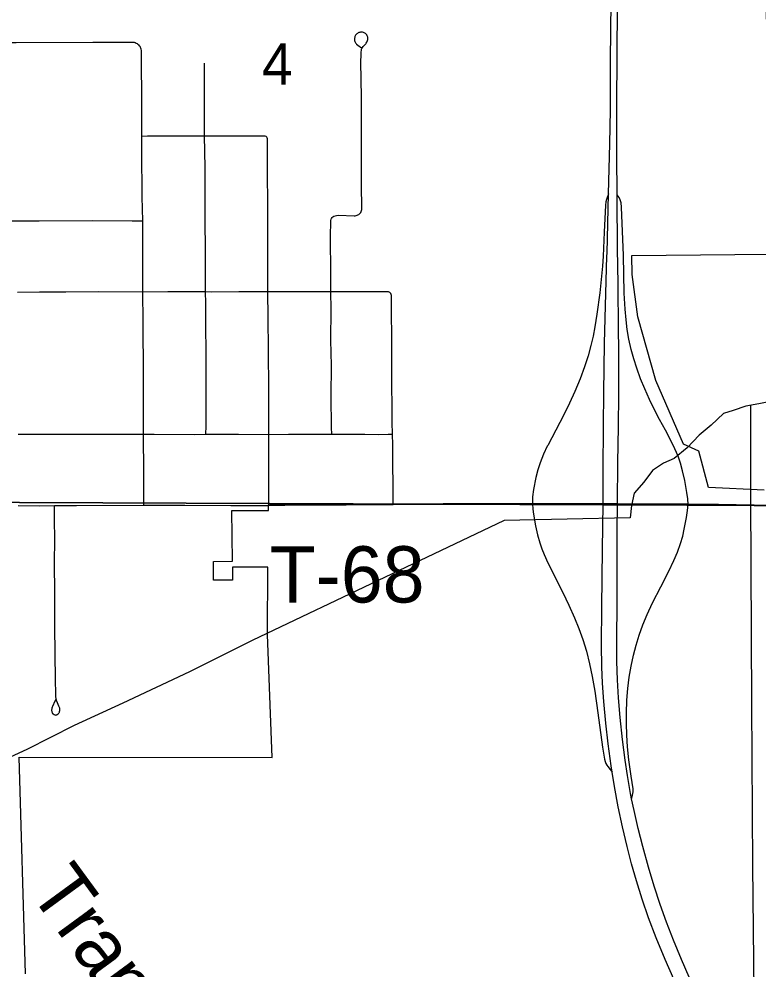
# Model space of a CAD drawing. Extents: x 0 to 40.2, y 0 to 22.
# Drawn here: x 4.998 to 5.744, y 14.848 to 15.808 of the extents above; entities that cross this region are included whole.
import ezdxf

# ---------------------------------------------------------------- set-up
doc = ezdxf.new("R2010")
doc.units = 0
for name, color, linetype in [('GM_X_City_Street', 7, 'Continuous'), ('GM_X_Corporation', 7, 'Continuous'), ('GM_X_County_Road_Text', 7, 'Continuous'), ('GM_X_Major_River_Text', 7, 'Continuous'), ('GM_X_Minor_Lake', 7, 'Continuous'), ('GM_X_Rail_Line', 7, 'Continuous'), ('GM_X_Unincorporated', 7, 'Continuous'), ('GM_X_Unincorporated_Location', 7, 'Continuous'), ('GM_X_US_Route', 7, 'Continuous')]:
    doc.layers.add(name, color=color, linetype=linetype)

msp = doc.modelspace()

# ---------------------------------------------------------------- linework, layer by layer
at = {"layer": 'GM_X_Corporation'}
for points in [[(5.74842, 16.25686), (5.75579, 15.31682), (4.745, 15.32081), (4.73985, 16.25627), (4.77053, 16.2552)], [(4.745, 15.32081), (5.75579, 15.31682), (5.76512, 14.30968), (4.74904, 14.31449)]]:
    msp.add_lwpolyline(points, close=True, dxfattribs=at)
for points in [[(5.74959, 15.33227), (5.69342, 15.33518), (5.68362, 15.37185), (5.6681, 15.37896), (5.64038, 15.44327), (5.62228, 15.50735), (5.61648, 15.55028), (5.61617, 15.56955), (5.75473, 15.57087)], [(5.0042, 14.84362), (4.99778, 15.0627), (5.25288, 15.0624), (5.24833, 15.18641), (5.24874, 15.25456), (5.21293, 15.25444), (5.21293, 15.24148), (5.1938, 15.24145), (5.19377, 15.26044), (5.2129, 15.26048), (5.21228, 15.31182), (5.24925, 15.31174), (5.24948, 15.31759), (5.26548, 15.31762), (5.32735, 15.31797), (5.37502, 15.31833), (5.42565, 15.31875), (5.42685, 15.31876), (5.51549, 15.31911), (5.57481, 15.31902), (5.58687, 15.31891), (5.60127, 15.31879), (5.63758, 15.31847), (5.67262, 15.3185), (5.70344, 15.31827), (5.73948, 15.31755), (5.75597, 15.31722)]]:
    msp.add_lwpolyline(points, dxfattribs=at)
at = {"layer": 'GM_X_Major_River_Text'}
for points in [[(5.59261, 15.63157), (5.5906, 15.62604), (5.59, 15.62363), (5.58939, 15.6201), (5.58824, 15.59307), (5.58725, 15.56876), (5.58659, 15.55857), (5.5837, 15.53167), (5.58091, 15.51009), (5.57888, 15.49719), (5.57709, 15.48803), (5.5748, 15.47835), (5.57195, 15.46817), (5.56832, 15.45692), (5.56384, 15.44466), (5.55866, 15.43199), (5.55327, 15.4201), (5.54745, 15.40841), (5.53119, 15.37761), (5.53076, 15.37671)], [(5.67285, 15.31794), (5.67246, 15.32345), (5.67164, 15.32988), (5.66948, 15.34212), (5.66733, 15.35183), (5.66514, 15.35961), (5.66271, 15.36666), (5.65958, 15.3741), (5.65552, 15.38249), (5.64993, 15.3929), (5.64402, 15.40383), (5.63973, 15.41211), (5.634, 15.42384), (5.62909, 15.43457), (5.62484, 15.44493), (5.62103, 15.45545), (5.61806, 15.46494), (5.6155, 15.47455), (5.61322, 15.48487), (5.6115, 15.49466), (5.61026, 15.50452), (5.60935, 15.51505), (5.60851, 15.5312), (5.60765, 15.56927), (5.60579, 15.61832), (5.6053, 15.62252), (5.60429, 15.62574), (5.60329, 15.62796), (5.6013, 15.63086)], [(5.53076, 15.37671), (5.52691, 15.36862), (5.52343, 15.35998), (5.52115, 15.35288), (5.51925, 15.34502), (5.51687, 15.33292), (5.51593, 15.32558), (5.51572, 15.31856)], [(5.51572, 15.31856), (5.51614, 15.31321), (5.51667, 15.30807), (5.51883, 15.29647), (5.52091, 15.28738), (5.52324, 15.279), (5.52522, 15.27312), (5.52746, 15.26733), (5.53139, 15.25888), (5.54655, 15.22894), (5.55265, 15.21603), (5.55815, 15.2035), (5.56258, 15.19256), (5.56665, 15.18148), (5.57032, 15.16961), (5.57349, 15.15695), (5.57613, 15.14418), (5.57864, 15.12947), (5.5818, 15.10732), (5.5865, 15.07284), (5.58845, 15.06057), (5.58911, 15.05828), (5.58999, 15.05621), (5.59095, 15.05445), (5.59182, 15.0531), (5.5941, 15.0501), (5.59622, 15.04732)], [(5.61591, 15.02067), (5.61685, 15.02419), (5.61719, 15.02587), (5.61742, 15.02755), (5.61746, 15.02902), (5.61736, 15.03071), (5.61535, 15.04336), (5.61312, 15.05999), (5.61175, 15.07296), (5.61093, 15.08474), (5.61055, 15.09653), (5.61059, 15.10709), (5.61114, 15.12012), (5.6121, 15.13189), (5.61354, 15.1436), (5.61537, 15.15463), (5.61768, 15.16557), (5.62033, 15.1758), (5.62343, 15.18589), (5.62723, 15.1964), (5.63155, 15.20671), (5.63709, 15.21852), (5.64525, 15.23458), (5.65343, 15.25064), (5.65845, 15.26131), (5.66211, 15.26988), (5.66532, 15.27863), (5.66743, 15.28577), (5.66906, 15.29304), (5.67117, 15.30478), (5.67216, 15.31182), (5.67285, 15.31794)]]:
    msp.add_lwpolyline(points, dxfattribs=at)
at = {"layer": 'GM_X_Minor_Lake'}
for points in [[(5.75447, 15.42161), (5.74423, 15.4195), (5.73132, 15.41706), (5.71839, 15.41271), (5.70851, 15.40984), (5.69622, 15.39789), (5.68395, 15.38785), (5.67202, 15.37514), (5.65899, 15.36435), (5.64794, 15.35959), (5.63685, 15.35218), (5.62834, 15.34056), (5.61833, 15.32934), (5.61586, 15.31686), (5.61453, 15.30436)], [(5.74043, 14.67702), (5.73999, 14.79276), (5.73835, 14.95291), (5.73716, 15.11646), (5.73631, 15.32554), (5.73624, 15.41799)], [(5.61453, 15.30436), (5.48737, 15.30186), (5.36653, 15.24424), (5.2335, 15.18075), (5.16943, 15.14878), (5.10235, 15.11723), (5.05318, 15.0945), (5.00551, 15.07023), (4.96207, 15.05044), (4.90609, 15.05096), (4.86182, 15.05092), (4.83658, 15.05739), (4.79141, 15.02435), (4.73825, 14.98803), (4.70954, 14.96649), (4.68877, 14.94519), (4.68027, 14.93357), (4.67593, 14.92263), (4.67861, 14.90058), (4.68093, 14.87968), (4.68138, 14.8607), (4.6766, 14.84484)]]:
    msp.add_lwpolyline(points, dxfattribs=at)
at = {"layer": 'GM_X_Rail_Line'}
msp.add_line((5.50277, 15.31851), (5.51572, 15.31856), dxfattribs=at)
for points in [[(4.99651, 15.31676), (5.01786, 15.31655), (5.03327, 15.31674)], [(5.03327, 15.31674), (5.05562, 15.31698), (5.12337, 15.31721)], [(5.12337, 15.31721), (5.16494, 15.3171), (5.21126, 15.31696)], [(5.21126, 15.31696), (5.21224, 15.31695), (5.2497, 15.31703)], [(5.2497, 15.31703), (5.26571, 15.31706), (5.32757, 15.31741), (5.37525, 15.31777)], [(5.37525, 15.31777), (5.42588, 15.31819), (5.42707, 15.3182), (5.50277, 15.31851)], [(5.51572, 15.31856), (5.57503, 15.31846), (5.5871, 15.31836), (5.60149, 15.31823), (5.6378, 15.31792), (5.67285, 15.31794)], [(5.67285, 15.31794), (5.70366, 15.31771), (5.73971, 15.317), (5.7562, 15.31667)]]:
    msp.add_lwpolyline(points, dxfattribs=at)
at = {"layer": 'GM_X_Unincorporated'}
for points in [[(5.59261, 15.63157), (5.59396, 15.68229), (5.59452, 15.71648), (5.59471, 15.76247), (5.59502, 15.80037), (5.5953, 15.82171), (5.59617, 15.93153), (5.59644, 15.97192), (5.59708, 16.01604), (5.59751, 16.05458), (5.59769, 16.08692), (5.59774, 16.14846), (5.59793, 16.17891), (5.59863, 16.25243), (5.59954, 16.34117), (5.59999, 16.39651)], [(5.60174, 15.573), (5.6013, 15.63086), (5.601, 15.67012), (5.60097, 15.72112), (5.6017, 15.82172)], [(5.58718, 15.32616), (5.58731, 15.35172), (5.58734, 15.39773), (5.58767, 15.43067), (5.58864, 15.48101), (5.59094, 15.56885), (5.59103, 15.57172), (5.59261, 15.63157)], [(5.6015, 15.31923), (5.60199, 15.36022), (5.60265, 15.39627), (5.60295, 15.42921), (5.60291, 15.46838), (5.6018, 15.56598), (5.60177, 15.56901), (5.60174, 15.573)], [(5.59622, 15.04732), (5.59515, 15.05392), (5.59208, 15.07606), (5.58971, 15.09705), (5.58779, 15.1187), (5.5866, 15.13729), (5.58595, 15.15404), (5.5856, 15.17578), (5.58568, 15.21432), (5.58634, 15.27275), (5.5871, 15.31836), (5.58715, 15.32125), (5.58718, 15.32616)], [(5.6738, 14.84051), (5.66613, 14.85822), (5.65809, 14.87779), (5.65114, 14.89579), (5.64462, 14.91395), (5.63858, 14.93228), (5.63286, 14.95136), (5.6271, 14.97237), (5.62256, 14.99049), (5.61836, 15.00868), (5.61591, 15.02067), (5.61487, 15.02576), (5.61159, 15.04415), (5.60924, 15.05953), (5.60654, 15.08053), (5.60433, 15.10283), (5.60279, 15.12268), (5.60175, 15.1407), (5.60111, 15.15937), (5.60092, 15.1799), (5.60117, 15.21909), (5.60136, 15.25452), (5.60118, 15.29181), (5.60149, 15.31823), (5.6015, 15.31923)], [(5.74645, 14.68727), (5.7284, 14.71332), (5.71567, 14.73246), (5.70512, 14.7493), (5.69373, 14.76854), (5.685, 14.78429), (5.67611, 14.80136), (5.66731, 14.81919), (5.6584, 14.83833), (5.64967, 14.85824), (5.64075, 14.88009), (5.63303, 14.90041), (5.62652, 14.91918), (5.62075, 14.93755), (5.6158, 14.95486), (5.61127, 14.97229), (5.60657, 14.99224), (5.60236, 15.0123), (5.59853, 15.03307), (5.59622, 15.04732)]]:
    msp.add_lwpolyline(points, dxfattribs=at)
at = {"layer": 'GM_X_Unincorporated_Location'}
for points in [[(5.31313, 15.38888), (5.31306, 15.39564), (5.31272, 15.42739), (5.31287, 15.45824), (5.31237, 15.48398), (5.31251, 15.51471), (5.31227, 15.53305), (5.31213, 15.54951), (5.31195, 15.58994), (5.31213, 15.60283), (5.31228, 15.60487), (5.31257, 15.60623), (5.313, 15.60696), (5.31351, 15.60771), (5.31425, 15.60845), (5.31524, 15.60907), (5.31648, 15.60964), (5.31787, 15.60993), (5.32012, 15.61001), (5.33584, 15.60959), (5.33669, 15.60964), (5.33785, 15.60983), (5.33877, 15.6101), (5.33967, 15.61046), (5.34048, 15.61089), (5.34132, 15.61142), (5.34193, 15.61207), (5.34255, 15.61298), (5.343, 15.61389), (5.34329, 15.61488), (5.34343, 15.61573), (5.34349, 15.61662), (5.3433, 15.64108), (5.34329, 15.65166), (5.34333, 15.6616), (5.34304, 15.68146), (5.34315, 15.70373), (5.3432, 15.72923), (5.3427, 15.76504), (5.34273, 15.77214), (5.34292, 15.77524), (5.3431, 15.77657), (5.34337, 15.77771), (5.34365, 15.77863), (5.34408, 15.7795), (5.34479, 15.78051), (5.34547, 15.78129), (5.34746, 15.78322), (5.34803, 15.784), (5.34861, 15.78493), (5.34904, 15.78573), (5.34935, 15.78665), (5.34954, 15.78749), (5.34966, 15.78841), (5.34963, 15.78909), (5.34947, 15.79002), (5.34923, 15.79079), (5.34894, 15.79144), (5.34854, 15.79221), (5.34805, 15.79289), (5.34741, 15.79356), (5.34663, 15.79406), (5.34595, 15.79443), (5.34515, 15.79471), (5.34416, 15.79492), (5.34336, 15.79498), (5.34234, 15.79498), (5.34145, 15.79486), (5.34068, 15.79458), (5.33985, 15.79424), (5.33907, 15.79384), (5.33846, 15.79341), (5.33781, 15.79277), (5.33729, 15.79205), (5.33689, 15.79137), (5.33651, 15.79057), (5.33633, 15.7898), (5.33622, 15.78903), (5.33612, 15.78829), (5.33614, 15.78731), (5.33624, 15.7865), (5.33643, 15.78573), (5.3367, 15.78504), (5.33714, 15.78431), (5.33769, 15.78363), (5.33831, 15.78295), (5.33939, 15.78202), (5.34323, 15.77931)], [(4.74173, 15.78431), (4.74969, 15.78421), (4.77457, 15.78415), (4.78699, 15.7841), (4.80502, 15.78424), (4.8274, 15.7843), (4.85016, 15.78436), (4.85661, 15.78438), (4.87962, 15.78453), (4.90385, 15.78447), (4.93183, 15.78443), (4.9455, 15.78438), (4.9685, 15.78457), (4.98652, 15.78457), (4.99451, 15.78458), (5.07187, 15.78481), (5.112, 15.78501), (5.11364, 15.7849), (5.1148, 15.7846), (5.11588, 15.78405), (5.11671, 15.78356), (5.11757, 15.78294), (5.11836, 15.7822)], [(5.12337, 15.31721), (5.12336, 15.32757), (5.12335, 15.34937), (5.12312, 15.38887), (5.123, 15.42184), (5.12299, 15.44825), (5.12274, 15.50241), (5.12243, 15.53276), (5.12246, 15.54038), (5.12261, 15.57032), (5.12252, 15.60323), (5.12248, 15.60447), (5.12193, 15.62856), (5.12158, 15.67504), (5.12153, 15.69013), (5.12149, 15.70005), (5.12132, 15.73023), (5.1213, 15.76302), (5.1213, 15.77519), (5.12113, 15.77638), (5.12084, 15.7777), (5.12051, 15.77873), (5.12014, 15.77967), (5.11965, 15.78062), (5.11913, 15.78134), (5.11836, 15.7822)], [(5.18624, 15.38876), (5.18626, 15.39717), (5.18627, 15.41766), (5.18632, 15.44035), (5.18655, 15.47334), (5.18605, 15.49629), (5.18593, 15.52079), (5.1858, 15.53289), (5.1857, 15.55255), (5.18562, 15.57974), (5.18547, 15.59963), (5.18549, 15.64005), (5.1855, 15.65818), (5.18486, 15.6902), (5.18487, 15.69918), (5.18477, 15.71718), (5.18475, 15.74577), (5.18479, 15.76363)], [(5.12153, 15.69013), (5.12712, 15.69014), (5.14825, 15.6902), (5.17872, 15.69019), (5.18486, 15.6902), (5.22039, 15.69034), (5.24579, 15.69014), (5.24669, 15.6899), (5.24764, 15.68905)], [(5.2497, 15.31703), (5.24972, 15.3235), (5.24979, 15.35588), (5.24964, 15.37828), (5.24968, 15.38872), (5.24973, 15.39917), (5.24955, 15.4338), (5.24921, 15.47402), (5.24911, 15.50635), (5.24869, 15.53305), (5.24876, 15.56648), (5.24857, 15.62192), (5.24831, 15.65236), (5.24823, 15.68732), (5.24808, 15.68832), (5.24764, 15.68905)], [(4.74236, 15.60381), (4.75074, 15.60388), (4.79856, 15.60429), (4.85089, 15.60428), (4.90189, 15.60422), (4.95002, 15.60432), (4.99529, 15.60451), (5.01779, 15.60459), (5.07187, 15.60464), (5.11165, 15.60451), (5.12248, 15.60447)], [(4.99587, 15.53249), (5.01808, 15.5327), (5.0448, 15.53276), (5.07764, 15.53318), (5.12243, 15.53276), (5.14756, 15.53296), (5.1858, 15.53289), (5.19198, 15.53287), (5.21932, 15.53295), (5.24869, 15.53305), (5.26655, 15.53311), (5.30382, 15.53306), (5.31227, 15.53305), (5.31749, 15.53304), (5.33364, 15.53302), (5.36838, 15.53319), (5.36944, 15.53313), (5.37005, 15.53304), (5.37073, 15.53282), (5.37135, 15.53248), (5.37196, 15.53208), (5.37254, 15.53148)], [(5.37525, 15.31777), (5.3749, 15.37831), (5.37459, 15.38888), (5.37423, 15.40119), (5.3738, 15.45416), (5.37379, 15.48616), (5.37362, 15.51252), (5.37344, 15.52838), (5.37336, 15.52915), (5.37326, 15.52986), (5.37289, 15.53097), (5.37254, 15.53148)], [(4.99666, 15.38887), (5.00684, 15.38901), (5.0155, 15.38905), (5.02916, 15.38892), (5.05524, 15.38877), (5.09606, 15.38883), (5.12312, 15.38887), (5.13397, 15.38879), (5.17499, 15.38867), (5.18624, 15.38876), (5.19737, 15.38885), (5.21913, 15.38881), (5.24968, 15.38872), (5.26946, 15.38894), (5.29743, 15.38888), (5.31313, 15.38888), (5.33099, 15.38888), (5.34653, 15.38889), (5.3602, 15.38875), (5.37012, 15.38884), (5.37459, 15.38888)], [(5.03452, 15.12092), (5.03362, 15.11918), (5.03135, 15.11389), (5.03094, 15.113), (5.0307, 15.11213), (5.03051, 15.11118), (5.03042, 15.11037), (5.03042, 15.10967), (5.03048, 15.10904), (5.03064, 15.10843), (5.03086, 15.10784), (5.03144, 15.10686), (5.03184, 15.10637), (5.03282, 15.10559), (5.03348, 15.10532), (5.03419, 15.10522), (5.03493, 15.10528), (5.03555, 15.10541), (5.03613, 15.10569), (5.03718, 15.10643), (5.03774, 15.10704), (5.03805, 15.1076), (5.03829, 15.10825), (5.03851, 15.10893), (5.03869, 15.10976), (5.03879, 15.11065), (5.03872, 15.11149), (5.03854, 15.11223), (5.03829, 15.11296), (5.03781, 15.11414), (5.0356, 15.11936), (5.03496, 15.12188), (5.03472, 15.12348), (5.03459, 15.12509), (5.03433, 15.14252), (5.03399, 15.16563), (5.03373, 15.19623), (5.03351, 15.22937), (5.0334, 15.25794), (5.03358, 15.28341), (5.03344, 15.30177), (5.03327, 15.31674)]]:
    msp.add_lwpolyline(points, dxfattribs=at)

# ---------------------------------------------------------------- texts
at = {"layer": 'GM_X_City_Street'}
msp.add_text('4', height=0.04186, rotation=0.00001, dxfattribs=at).set_placement((5.24269, 15.74201))
at = {"layer": 'GM_X_County_Road_Text'}
msp.add_text('T-68', height=0.056818, rotation=0.00001, dxfattribs=at).set_placement((5.2506, 15.21886))
at = {"layer": 'GM_X_US_Route'}
msp.add_text('Transportation, Inc.', height=0.0566288, rotation=306.20463, dxfattribs=at).set_placement((5.00635, 14.92707))

doc.saveas('drawing.dxf')
